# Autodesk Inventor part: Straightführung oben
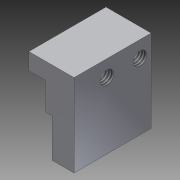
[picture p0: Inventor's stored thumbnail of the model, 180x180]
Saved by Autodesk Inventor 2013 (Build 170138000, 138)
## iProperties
Created: 2012-07
Part Number: Straightführung oben
Material: PC/ABS-Kunststoff
Document SubType Name: Modeling
Designer: rYan
Mass: 0.844412 g
Surface Area: 5.50809 cm^2
Volume: 0.565581 cm^3
Density: 1.493 g/cm^3
Author: rYan
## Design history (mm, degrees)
sketch "Skizze1"
  geometry: L1 (0, 0)-(-5.2, 0); L2 (-5.2, 8)-(3, 8); L3 (0, 5)-(0, 0); L4 (3, 8)-(3, 5); L5 (3, 5)-(0, 5); L6 (-5.2, 0)-(-5.2, 8)
  constraints: 12 end point, 3 vertical, 2 horizontal, 1 coincident, 1 parallel, 1 point on line, 2 other
  dimensions: "d1" = 3 distance of L2.end L4.end; "d2" = 5 distance of L3.start L1.start; "d3" = 3 distance of L4.end L3.start; "d19" = 5.2 distance between parallel lines of L3 L6
extrude "Extrusion1" new body sketch "Skizze1" distance "d4" = 6; taper "d5" = 0 deg
mirror "Spiegeln1"
sketch "Skizze2"
  geometry: L1 (0, 0)-(0, 6) reference; L2 (0, 0)-(8, 0) reference; 2 further points
  constraints: 1 symmetric about line
  dimensions: "d8" = 6 distance of point (2.5, 3) point (2.5, -3); "d22" = 2.5 distance from line of L1 point (2.5, 3) (= d20)
hole "Bohrung1" sketch "Skizze2" at (2.5, -3), (2.5, 3) diameter "d9" = 2.459; stored, may be unused: countersink angle "d13" = 90 deg, drill point angle "d15" = 118 deg; dims "d10" = 6, "d11" = 4, "d12" = 2, "d14" = 4
fillet "Rundung1" dims "d26" = 1
node "Volumenkörper1"
other parameters: "d20" = 2.5
